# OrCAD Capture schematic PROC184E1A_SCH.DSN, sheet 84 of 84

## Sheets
84 62. AUDIO I/F - STEREO MIC #1: size C; title: AUDIO I/F - STEREO MIC #1; note: PROC184_SCH
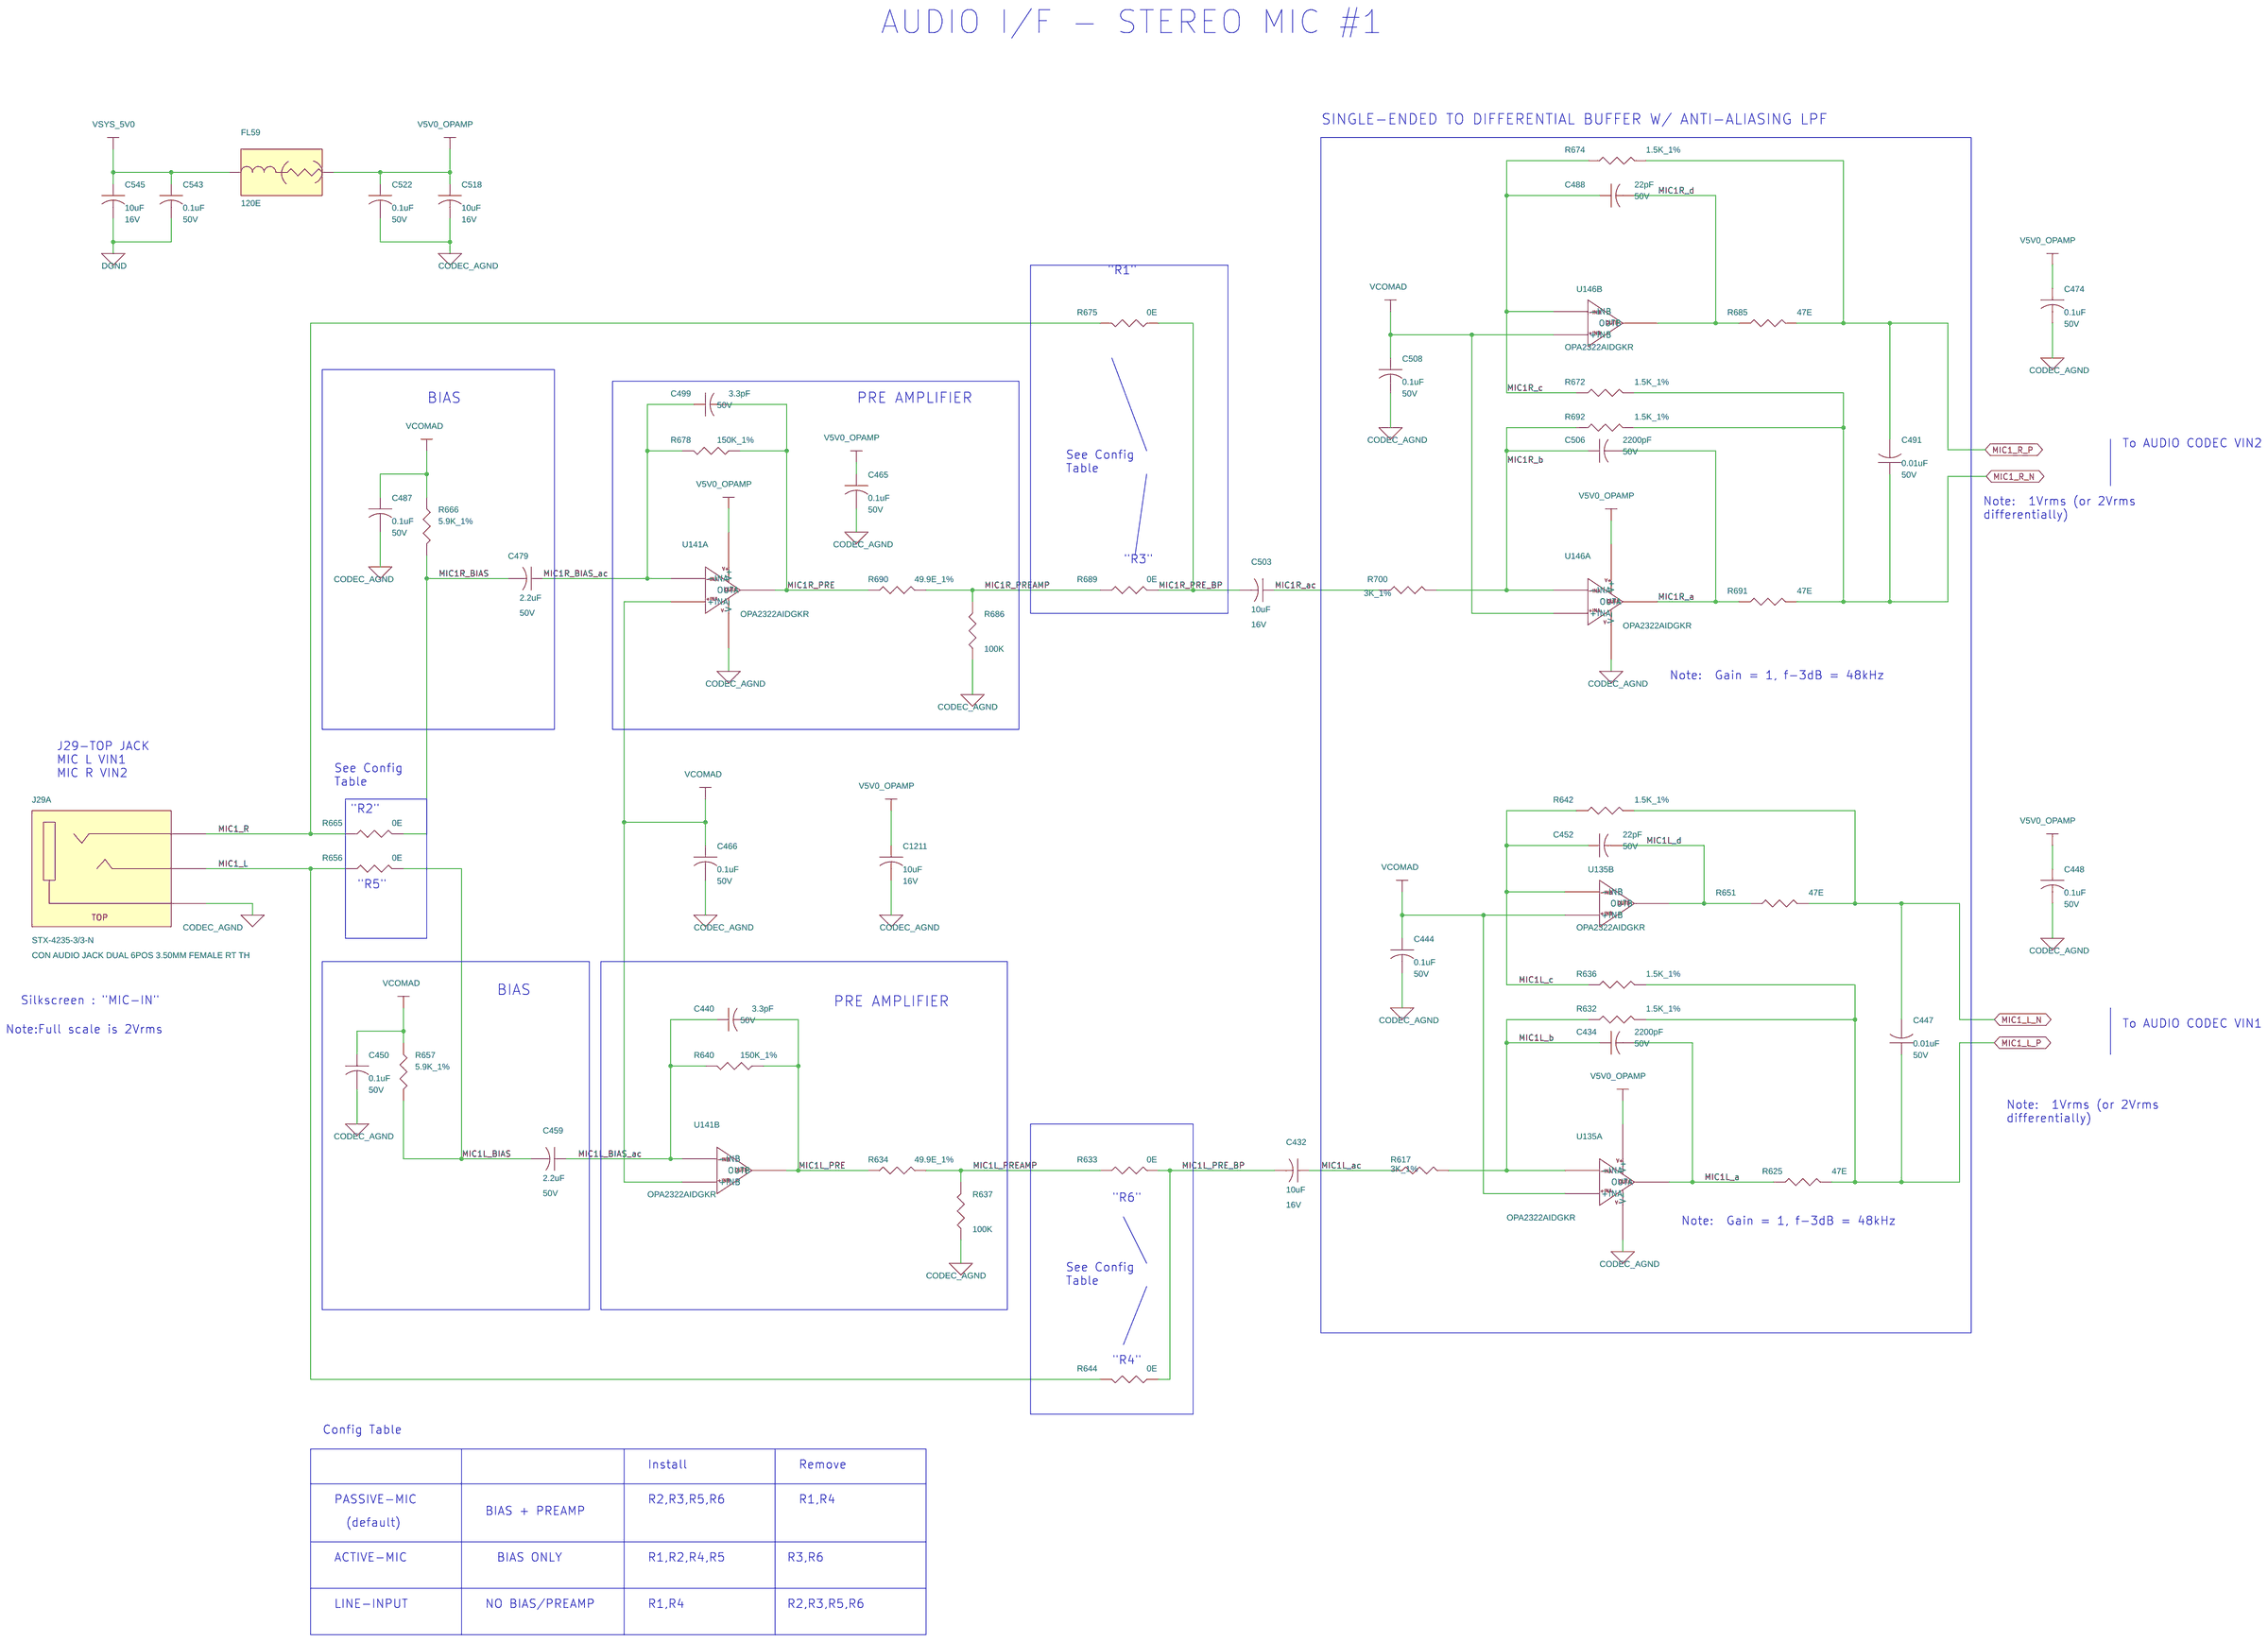
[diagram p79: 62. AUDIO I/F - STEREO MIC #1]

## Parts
C432  10uF  [CAP0805_1-5]
C434  2200pF  [CAP0805_1-5]
C440  3.3pF  [CAP0402_0-75]
C444  0.1uF  [CAP0402_0-75]
C447  0.01uF  [CAP0402_0-75]
C448  0.1uF  [CAP0402_0-75]
C450  0.1uF  [CAP0402_0-75]
C452  22pF  [CAP0402_0-75]
C459  2.2uF  [CAP0805_1-5]
C465  0.1uF  [CAP0402_0-75]
C466  0.1uF  [CAP0402_0-75]
C474  0.1uF  [CAP0402_0-75]
C479  2.2uF  [CAP0805_1-5]
C487  0.1uF  [CAP0402_0-75]
C488  22pF  [CAP0402_0-75]
C491  0.01uF  [CAP0402_0-75]
C499  3.3pF  [CAP0402_0-75]
C503  10uF  [CAP0805_1-5]
C506  2200pF  [CAP0805_1-5]
C508  0.1uF  [CAP0402_0-75]
C518  10uF  [CAP0805_1-5]
C522  0.1uF  [CAP0402_0-75]
C543  0.1uF  [CAP0402_0-75]
C545  10uF  [CAP0805_1-5]
C1211  10uF  [CAP0805_1-5]
FL59  120E  [EMIFIL_BLM15A_0402_0-6]
J29  CON_AUDIOJACK6_STX-4235  [CON_AV6_STX-4235-3-3_S_R_T_26]  (sections A,B)
R617  3K_1%  [RES0402_0-5]
R625  47E  [RES0402_0-5]
R632  1.5K_1%  [RES0402_0-5]
R633  0E  [RES0402_0-5]
R634  49.9E_1%  [RES0402_0-5]
R636  1.5K_1%  [RES0402_0-5]
R637  100K  [RES0402_0-5]
R640  150K_1%  [RES0402_0-5]
R642  1.5K_1%  [RES0402_0-5]
R644  0E  [RES0402_0-5]
R651  47E  [RES0402_0-5]
R656  0E  [RES0402_0-5]
R657  5.9K_1%  [RES0402_0-5]
R665  0E  [RES0402_0-5]
R666  5.9K_1%  [RES0402_0-5]
R672  1.5K_1%  [RES0402_0-5]
R674  1.5K_1%  [RES0402_0-5]
R675  0E  [RES0402_0-5]
R678  150K_1%  [RES0402_0-5]
R685  47E  [RES0402_0-5]
R686  100K  [RES0402_0-5]
R689  0E  [RES0402_0-5]
R690  49.9E_1%  [RES0402_0-5]
R691  47E  [RES0402_0-5]
R692  1.5K_1%  [RES0402_0-5]
R700  3K_1%  [RES0402_0-5]
U135  OPA2322AIDGKR  [VSSOP8_25-59_120X120_1-1]  (sections A,B)
U141  OPA2322AIDGKR  [VSSOP8_25-59_120X120_1-1]  (sections A,B)
U146  OPA2322AIDGKR  [VSSOP8_25-59_120X120_1-1]  (sections A,B)

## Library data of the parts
C432 C503 C518 C545 C1211 = CAP: CAP CERAMIC 10uF 16V 10% X5R 0805; Automotive Alternate_mfr_name: TDK; Automotive Alternate_mfr_part_number: CGA4J1X7S1C106K125AC; Chkd/date: SHREESHAIL/220506; Crtd /date: MAZHAR/150506; Custom_Duty: 15%; Customs_HS_Code: 85322990; Direct Alternate_mfr_name: TDK; Direct Alternate_mfr_part_number: C2012X7S1C106K125AC; Distributor_name: DIGIKEY; Distributor_part_number: 490-3886-1-ND; Footprint Path: Y:\MIS_DATABASE\Library\ALTIUM_TOOL\PCB_FOOTPRINTS\Altium_Footprint_Lib.PcbLib; Height: 1.35MM; Library Path: Y:\MIS_DATABASE\Library\ALTIUM_TOOL\SCHEMATICS_PARTS\MS_DISCRETE_Library.schlib; Manufacturer: MURATA; Mfr_name: MURATA; Mfr_part_number: GRM21BR61C106KE15L; Mistral Part No: 120009030205-R; Package: 0805; Part_type: CAPACITORS\CERAMIC; Project: VOCERA; RoHS: RoHS; Temperature: -55°C+85°C; Tolerance: 10%; Voltage: 16V; Wattage: NA; Weight: 9.5mg; Datasheet: Y:\MIS_DATABASE\DATASHEETS\CAPACITORS\MURATA-GXX-SER_NOV17.PDF
C434 C506 = CAP: CAP CERAMIC 2200pF 50V 1% C0G(NP0) 0805; Automotive Alternate_mfr_name: TDK; Automotive Alternate_mfr_part_number: CGA4C2C0G1H222J060AA; Chkd/date: MANIRAJA/070619; Crtd /date: MANIRAJA/070619; Custom_Duty: 15%; Customs_HS_Code: 85322990; Direct Alternate_mfr_name: TDK; Direct Alternate_mfr_part_number: C2012C0G1H222J060AA; Distributor_name: DIGIKEY; Distributor_part_number: 311-4157-1-ND; Footprint Path: Y:\MIS_DATABASE\Library\ALTIUM_TOOL\PCB_FOOTPRINTS\Altium_Footprint_Lib.PcbLib; Height: 1.45MM; Library Path: Y:\MIS_DATABASE\Library\ALTIUM_TOOL\SCHEMATICS_PARTS\MS_DISCRETE_Library.schlib; Manufacturer: YAGEO AMERICA; Mfr_name: YAGEO AMERICA; Mfr_part_number: CC0805FKNPO9BN222; Mistral Part No: 120011120002-R; Package: 0805; Part_type: CAPACITORS\CERAMIC; Project: J7ES_SOM_DUAL-LEO_PMIC; RoHS: RoHS; Temperature: -55°C+125°C; Tolerance: 1%; Voltage: 50V; Wattage: NA; Weight: 5.5mg; Datasheet: Y:\MIS_DATABASE\DATASHEETS\CAPACITORS\YACC-NPO.PDF
C440 C499 = CAP: CAP CERAMIC 3.3pF 50V 0.25pF C0G(NP0) 0402; Automotive Alternate_mfr_name: TDK; Automotive Alternate_mfr_part_number: CGA2B2C0G1H3R3C050BA; Chkd/date: SHREESHAIL/281105; Crtd /date: MAZHAR/211005; Custom_Duty: 15%; Customs_HS_Code: 85322990; Direct Alternate_mfr_name: SAMSUNG; Direct Alternate_mfr_part_number: CL05C3R3CB5NNNC; Distributor_name: DIGIKEY; Distributor_part_number: 478-1064-1-ND; Footprint Path: Y:\MIS_DATABASE\Library\ALTIUM_TOOL\PCB_FOOTPRINTS\Altium_Footprint_Lib.PcbLib; Height: 0.56MM; Library Path: Y:\MIS_DATABASE\Library\ALTIUM_TOOL\SCHEMATICS_PARTS\MS_DISCRETE_Library.schlib; Manufacturer: AVX CORPORATION; Mfr_name: AVX CORPORATION; Mfr_part_number: 04025A3R3CAT2A; Mistral Part No: 120009030354-R; Package: 0402; Part_type: CAPACITORS\CERAMIC; Project: EPDA_CORE; RoHS: RoHS; Temperature: -55°C+125°C; Tolerance: 0.25pF%; Voltage: 50V; Wattage: NA; Weight: 0.65mg; Datasheet: Y:\MIS_DATABASE\DATASHEETS\CAPACITORS\AVX_MLC.PDF
C444 C448 C450 C465 C466 C474 C487 C508 C522 C543 = CAP: CAP CERAMIC 0.1uF 50V 10% X7R 0402; Automotive Alternate_mfr_name: TDK; Automotive Alternate_mfr_part_number: CGA2B3X7R1H104K050BB; Chkd/date: MANIRAJA/261020; Crtd /date: ALVY/211020; Custom_Duty: 15%; Customs_HS_Code: 85322990; Direct Alternate_mfr_name: TDK; Direct Alternate_mfr_part_number: C1005X7R1H104K050BE; Distributor_name: DIGIKEY; Distributor_part_number: 490-10700-1-ND; Footprint Path: Y:\MIS_DATABASE\Library\ALTIUM_TOOL\PCB_FOOTPRINTS\Altium_Footprint_Lib.PcbLib; Height: 0.55MM; Library Path: Y:\MIS_DATABASE\Library\ALTIUM_TOOL\SCHEMATICS_PARTS\MS_DISCRETE_Library.schlib; Manufacturer: MURATA; Mfr_name: MURATA; Mfr_part_number: GRM155R71H104KE14D; Mistral Part No: 120011100014-R; Package: 0402; Part_type: CAPACITORS\CERAMIC; Project: J7_CP; RoHS: RoHS; Temperature: -55°C+125°C; Tolerance: 10%; Voltage: 50V; Wattage: NA; Weight: 3.1mg; Datasheet: Y:\MIS_DATABASE\DATASHEETS\CAPACITORS\GRM155R71H104KE14.PDF
C447 C491 = CAP: CAP CERAMIC 0.01uF 50V 10% X7R 0402; Automotive Alternate_mfr_name: TDK; Automotive Alternate_mfr_part_number: CGA2B2X7R1E103K050BA; Chkd/date: MANIRAJA/280319; Crtd /date: MANIRAJA/280319; Custom_Duty: 15%; Customs_HS_Code: 85322990; Direct Alternate_mfr_name: YAGEO AMERICA; Direct Alternate_mfr_part_number: CC0402KRX7R8BB103; Distributor_name: DIGIKEY; Distributor_part_number: 490-4516-1-ND; Footprint Path: Y:\MIS_DATABASE\Library\ALTIUM_TOOL\PCB_FOOTPRINTS\Altium_Footprint_Lib.PcbLib; Height: 0.55MM; Library Path: Y:\MIS_DATABASE\Library\ALTIUM_TOOL\SCHEMATICS_PARTS\MS_DISCRETE_Library.schlib; Manufacturer: MURATA; Mfr_name: MURATA; Mfr_part_number: GRM155R71H103KA88D; Mistral Part No: 120009030025-R; Package: 0402; Part_type: CAPACITORS\CERAMIC; Project: G4_SVGA; RoHS: RoHS; Temperature: -55°C+125°C; Tolerance: 10%; Voltage: 50V; Wattage: NA; Weight: 0.65mg; Datasheet: Y:\MIS_DATABASE\DATASHEETS\CAPACITORS\GRM155R71H103KA88D.PDF
C452 C488 = CAP: CAP CERAMIC 22pF 50V 5% C0G(NP0) 0402; Automotive Alternate_mfr_name: TDK; Automotive Alternate_mfr_part_number: CGA2B2C0G1H220J050BA; Chkd/date: MANIRAJA/060619; Crtd /date: MANIRAJA/060619; Custom_Duty: 15%; Customs_HS_Code: 85322990; Direct Alternate_mfr_name: TDK; Direct Alternate_mfr_part_number: C1005NP01H220J050BA; Distributor_name: DIGIKEY; Distributor_part_number: 1276-1116-1-ND; Footprint Path: Y:\MIS_DATABASE\Library\ALTIUM_TOOL\PCB_FOOTPRINTS\Altium_Footprint_Lib.PcbLib; Height: 0.55MM; Library Path: Y:\MIS_DATABASE\Library\ALTIUM_TOOL\SCHEMATICS_PARTS\MS_DISCRETE_Library.schlib; Manufacturer: SAMSUNG; Mfr_name: SAMSUNG; Mfr_part_number: CL05C220JB5NNNC; Mistral Part No: 120014100023-R; Package: 0402; Part_type: CAPACITORS\CERAMIC; Project: J7ES_SOM_DUAL-LEO_PMIC; RoHS: RoHS; Temperature: -55°C+125°C; Tolerance: 5%; Voltage: 50V; Wattage: NA; Weight: 0.65mg; Datasheet: Y:\MIS_DATABASE\DATASHEETS\CAPACITORS\CL05C220JB5NNNC.PDF
C459 C479 = CAP: CAP CERAMIC 2.2uF 50V 20% X7R 0805; Automotive Alternate_mfr_name: TDK; Automotive Alternate_mfr_part_number: CGA4J3X7R1H225K125AB; Chkd/date: MANIRAJA/241018; Crtd /date: ALVY/241018; Custom_Duty: 15%; Customs_HS_Code: 85322990; Direct Alternate_mfr_name: YAGEO AMERICA; Direct Alternate_mfr_part_number: CC0805KKX7R9BB225; Distributor_name: DIGIKEY; Distributor_part_number: 445-172488-1-ND; Footprint Path: Y:\MIS_DATABASE\Library\ALTIUM_TOOL\PCB_FOOTPRINTS\Altium_Footprint_Lib.PcbLib; Height: 1.50MM; Library Path: Y:\MIS_DATABASE\Library\ALTIUM_TOOL\SCHEMATICS_PARTS\MS_DISCRETE_Library.schlib; Manufacturer: TDK CORPORATION; Mfr_name: TDK CORPORATION; Mfr_part_number: C2012X7R1H225M125AE; Mistral Part No: 120018100054-R; Package: 0805; Part_type: CAPACITORS\CERAMIC; Project: TI_J7ES_EVM_CP; RoHS: RoHS; Temperature: -55°C+125°C; Tolerance: 20%; Voltage: 50V; Wattage: NA; Weight: 5.5mg; Datasheet: Y:\MIS_DATABASE\DATASHEETS\CAPACITORS\TDK-CAP-E-SER.PDF
FL59 = EMIFILTER_IND: IND FERRITE BEAD CHIP 120E 1.3A 0402; Automotive Alternate_mfr_name: TDK; Automotive Alternate_mfr_part_number: MPZ1005S121CTD25; Chkd/date: VASANTHA/010117; Crtd /date: CHAITHANYA/150312; Custom_Duty: 24%; Customs_HS_Code: 85437099; Direct Alternate_mfr_name: TDK; Direct Alternate_mfr_part_number: MPZ1005S121CT000; Distributor_name: DIGIKEY; Distributor_part_number: 490-5203-1-ND; Footprint Path: Y:\MIS_DATABASE\Library\ALTIUM_TOOL\PCB_FOOTPRINTS\Altium_Footprint_Lib.PcbLib; Height: 0.55MM; Library Path: Y:\MIS_DATABASE\Library\ALTIUM_TOOL\SCHEMATICS_PARTS\MS_FILTER_Library.schlib; Manufacturer: MURATA; Mfr_name: MURATA; Mfr_part_number: BLM15PD121SN1D; Mistral Part No: 130012030043-R; Package: 0402; Part_type: FILTER; Project: GEN_3-8; RoHS: RoHS; Temperature: -55°C+125°C; Tolerance: 25%; Voltage: NA; Wattage: NA; Weight: 0.65mg; Datasheet: Y:\MIS_DATABASE\DATASHEETS\DISCRETES\INDUCTORS\BLM15X-SER.PDF
J29 = CON_AUDIOJACK6_STX-4235-3_3: CON AUDIO JACK DUAL 6POS 3.50MM FEMALE RT TH; Chkd/date: MANIRAJA/090818; Crtd /date: ALVY/080818; Custom_Duty: 24%; Customs_HS_Code: 85369090; Distributor_name: MOUSER; Distributor_part_number: 806-STX-4235-3/3-N; Footprint Path: Y:\MIS_DATABASE\Library\ALTIUM_TOOL\PCB_FOOTPRINTS\Altium_Footprint_Lib.PcbLib; Height: 26.00MM; Library Path: Y:\MIS_DATABASE\Library\ALTIUM_TOOL\SCHEMATICS_PARTS\MS_CONNECTOR_Library.schlib; Library Ref: CON_AUDIOJACK6_STX-4235-3/3; Manufacturer: KYCON; Mfr_name: KYCON; Mfr_part_number: STX-4235-3/3-N; Mistral Part No: 150018080005-R; Package: THRU-HOLE; Part_type: CONNECTOR\JACK; Project: TI_J7ES_EVM_FUSION2_SER_CAP; RoHS: RoHS; Temperature: -25°C+85°C; Tolerance: NA; Voltage: NA; Wattage: NA; Weight: NA; Datasheet: Y:\MIS_DATABASE\DATASHEETS\CONNECTORS\STX-4235-3-3-N.PDF
R617 R700 = RESISTOR: RES 3K 1/16W 1% 0402; Chkd/date: MANIRAJA/101117; Crtd /date: MANIRAJA/101117; Custom_Duty: 15%; Customs_HS_Code: 85332119; Distributor_name: DIGIKEY; Distributor_part_number: 311-3KLRCT-ND; Footprint Path: Y:\MIS_DATABASE\Library\ALTIUM_TOOL\PCB_FOOTPRINTS\Altium_Footprint_Lib.PcbLib; Height: 0.40MM; Library Path: Y:\MIS_DATABASE\Library\ALTIUM_TOOL\SCHEMATICS_PARTS\MS_DISCRETE_Library.schlib; Manufacturer: PANASONIC-ECG; Mfr_name: YAGEO AMERICA; Mfr_part_number: RC0402FR-073KL; Mistral Part No: 110017110004-R; Package: 0402; Part_type: RESISTORS\FIXED; Project: TI_SVB_MAXWELL_DUT; RoHS: RoHS; Temperature: -55°C+155°C; Tolerance: 1%; Voltage: NA; Wattage: 1/16W; Weight: 0.65mg; Datasheet: Y:\MIS_DATABASE\DATASHEETS\RESISTORS\RCXXXXL-SER_MAR18.PDF
R625 R651 R685 R691 = RESISTOR: RES 47E 1/16W 5% 0402; Chkd/date: MANIRAJA/250319; Crtd /date: MANIRAJA/250319; Custom_Duty: 15%; Customs_HS_Code: 85332119; Distributor_name: DIGIKEY; Distributor_part_number: 311-47JRCT-ND; Footprint Path: Y:\MIS_DATABASE\Library\ALTIUM_TOOL\PCB_FOOTPRINTS\Altium_Footprint_Lib.PcbLib; Height: 0.40MM; Library Path: Y:\MIS_DATABASE\Library\ALTIUM_TOOL\SCHEMATICS_PARTS\MS_DISCRETE_Library.schlib; Manufacturer: YAGEO AMERICA; Mfr_name: YAGEO AMERICA; Mfr_part_number: RC0402JR-0747RL; Mistral Part No: 110019040221-R; Package: 0402; Part_type: RESISTORS\FIXED; Project: POWERBOX; RoHS: RoHS; Temperature: -55°C+155°C; Tolerance: 5%; Voltage: NA; Wattage: 1/16W; Weight: 0.65mg; Datasheet: Y:\MIS_DATABASE\DATASHEETS\RESISTORS\RCXXXXL-SER_MAR18.PDF
R632 R636 R642 R672 R674 R692 = RESISTOR: RES 1.5K 1/16W 1% 0402; Chkd/date: VASANTHA/201216; Crtd /date: JEBRAN/250815; Custom_Duty: 15%; Customs_HS_Code: 85332119; Distributor_name: DIGIKEY; Distributor_part_number: 311-1.50KLRCT-ND; Footprint Path: Y:\MIS_DATABASE\Library\ALTIUM_TOOL\PCB_FOOTPRINTS\Altium_Footprint_Lib.PcbLib; Height: 0.40MM; Library Path: Y:\MIS_DATABASE\Library\ALTIUM_TOOL\SCHEMATICS_PARTS\MS_DISCRETE_Library.schlib; Manufacturer: YAGEO AMERICA; Mfr_name: YAGEO AMERICA; Mfr_part_number: RC0402FR-071K5L; Mistral Part No: 110015080041-R; Package: 0402; Part_type: RESISTORS\FIXED; Project: OCTBTS3600; RoHS: RoHS; Temperature: -55°C+155°C; Tolerance: 1%; Voltage: NA; Wattage: 1/16W; Weight: 0.65mg; Datasheet: Y:\MIS_DATABASE\DATASHEETS\RESISTORS\RCXXXXL-SER_MAR18.PDF
R633 R656 R665 R689 = RESISTOR: RES 0E 1/10W JUMPER 0402; Chkd/date: VASANTHA/061216; Crtd /date: NAVEED/201014; Custom_Duty: 15%; Customs_HS_Code: 85332119; Distributor_name: DIGIKEY; Distributor_part_number: P0.0JCT-ND; Footprint Path: Y:\MIS_DATABASE\Library\ALTIUM_TOOL\PCB_FOOTPRINTS\Altium_Footprint_Lib.PcbLib; Height: 0.40MM; IBISSP_MODLES: VALUE REPEATING 2 TIME; Library Path: Y:\MIS_DATABASE\Library\ALTIUM_TOOL\SCHEMATICS_PARTS\MS_DISCRETE_Library.schlib; Manufacturer: PANASONIC-ECG; Mfr_name: PANASONIC-ECG; Mfr_part_number: ERJ-2GE0R00X; Mistral Part No: 110018030052-R; Package: 0402; Part_type: RESISTORS\FIXED; Project: AEGIS POM; RoHS: RoHS; Temperature: -55°C+155°C; Tolerance: NA; Voltage: NA; Wattage: 1/10W; Weight: 0.8mg; Datasheet: Y:\MIS_DATABASE\DATASHEETS\RESISTORS\PAN-ERJSER_NOV17.PDF
R634 R690 = RESISTOR: RES 49.9E 1/10W 1% 0402; Chkd/date: VASANTHA/201216; Crtd /date: MAZHAR/201005; Custom_Duty: 15%; Customs_HS_Code: 85332119; Distributor_name: DIGIKEY; Distributor_part_number: P49.9LCT-ND; Footprint Path: Y:\MIS_DATABASE\Library\ALTIUM_TOOL\PCB_FOOTPRINTS\Altium_Footprint_Lib.PcbLib; Height: 0.40MM; Library Path: Y:\MIS_DATABASE\Library\ALTIUM_TOOL\SCHEMATICS_PARTS\MS_DISCRETE_Library.schlib; Manufacturer: PANASONIC-ECG; Mfr_name: PANASONIC-ECG; Mfr_part_number: ERJ-2RKF49R9X; Mistral Part No: 110009030897-R; Package: 0402; Part_type: RESISTORS\FIXED; Project: RED EYE; RoHS: RoHS; Temperature: -55°C+155°C; Tolerance: 1%; Voltage: NA; Wattage: 1/10W; Weight: 0.8mg; Datasheet: Y:\MIS_DATABASE\DATASHEETS\RESISTORS\PAN-ERJSER_NOV17.PDF
R637 R686 = RESISTOR: RES 100K 1/10W 5% 0402; Assembly_Instruction: DNI; Chkd/date: VASANTHA/291216; Crtd /date: GEETHA/190406; Custom_Duty: 15%; Customs_HS_Code: 85332119; Distributor_name: DIGIKEY; Distributor_part_number: P100KJCT-ND; Footprint Path: Y:\MIS_DATABASE\Library\ALTIUM_TOOL\PCB_FOOTPRINTS\Altium_Footprint_Lib.PcbLib; Height: 0.40MM; Library Path: Y:\MIS_DATABASE\Library\ALTIUM_TOOL\SCHEMATICS_PARTS\MS_DISCRETE_Library.schlib; Manufacturer: PANASONIC-ECG; Mfr_name: PANASONIC-ECG; Mfr_part_number: ERJ-2GEJ104X; Mistral Part No: 110009030177-R; Package: 0402; Part_type: RESISTORS\FIXED; Project: RED EYE; RoHS: RoHS; Temperature: -55°C+155°C; Tolerance: 5%; Voltage: NA; Wattage: 1/10W; Weight: 0.8mg; Datasheet: Y:\MIS_DATABASE\DATASHEETS\RESISTORS\PAN-ERJSER_NOV17.PDF
R640 R678 = RESISTOR: RES 150K 1/10W 1% 0402; Chkd/date: SHREESHAIL/200906; Crtd /date: MAZHAR/190906; Custom_Duty: 15%; Customs_HS_Code: 85332119; Distributor_name: DIGIKEY; Distributor_part_number: P150KLCT-ND; Footprint Path: Y:\MIS_DATABASE\Library\ALTIUM_TOOL\PCB_FOOTPRINTS\Altium_Footprint_Lib.PcbLib; Height: 0.40MM; Library Path: Y:\MIS_DATABASE\Library\ALTIUM_TOOL\SCHEMATICS_PARTS\MS_DISCRETE_Library.schlib; Manufacturer: PANASONIC-ECG; Mfr_name: PANASONIC-ECG; Mfr_part_number: ERJ-2RKF1503X; Mistral Part No: 110009030336-R; Package: 0402; Part_type: RESISTORS\FIXED; Project: SM2_AFE; RoHS: RoHS; Temperature: -55°C+155°C; Tolerance: 1%; Voltage: NA; Wattage: 1/10W; Weight: 0.8mg; Datasheet: Y:\MIS_DATABASE\DATASHEETS\RESISTORS\PAN-ERJSER_NOV17.PDF
R644 R675 = RESISTOR: RES 0E 1/10W JUMPER 0402; Assembly_Instruction: DNI; Chkd/date: VASANTHA/061216; Crtd /date: NAVEED/201014; Custom_Duty: 15%; Customs_HS_Code: 85332119; Distributor_name: DIGIKEY; Distributor_part_number: P0.0JCT-ND; Footprint Path: Y:\MIS_DATABASE\Library\ALTIUM_TOOL\PCB_FOOTPRINTS\Altium_Footprint_Lib.PcbLib; Height: 0.40MM; IBISSP_MODLES: VALUE REPEATING 2 TIME; Library Path: Y:\MIS_DATABASE\Library\ALTIUM_TOOL\SCHEMATICS_PARTS\MS_DISCRETE_Library.schlib; Manufacturer: PANASONIC-ECG; Mfr_name: PANASONIC-ECG; Mfr_part_number: ERJ-2GE0R00X; Mistral Part No: 110018030052-R; Package: 0402; Part_type: RESISTORS\FIXED; Project: AEGIS POM; RoHS: RoHS; Temperature: -55°C+155°C; Tolerance: NA; Voltage: NA; Wattage: 1/10W; Weight: 0.8mg; Datasheet: Y:\MIS_DATABASE\DATASHEETS\RESISTORS\PAN-ERJSER_NOV17.PDF
R657 R666 = RESISTOR: RES 5.9K 1/10W 1% 0402; Chkd/date: MAZHAR/251110; Crtd /date: BAVISH/251110; Custom_Duty: 15%; Customs_HS_Code: 85332119; Distributor_name: DIGIKEY; Distributor_part_number: P5.90KLCT-ND; Footprint Path: Y:\MIS_DATABASE\Library\ALTIUM_TOOL\PCB_FOOTPRINTS\Altium_Footprint_Lib.PcbLib; Height: 0.40MM; Library Path: Y:\MIS_DATABASE\Library\ALTIUM_TOOL\SCHEMATICS_PARTS\MS_DISCRETE_Library.schlib; Manufacturer: PANASONIC-ECG; Mfr_name: PANASONIC-ECG; Mfr_part_number: ERJ-2RKF5901X; Mistral Part No: 110010110029-R; Package: 0402; Part_type: RESISTORS\FIXED; Project: CENTAURUS; RoHS: RoHS; Temperature: -55°C+155°C; Tolerance: 1%; Voltage: NA; Wattage: 1/10W; Weight: 0.8mg; Datasheet: Y:\MIS_DATABASE\DATASHEETS\RESISTORS\PAN-ERJSER_NOV17.PDF
U135 U141 U146 = OPA2350UA_SOIC8: IC 20MHz 1.8V LOW NOISE RRI/O CMOS OPAMP VSSOP8; Automotive Alternate_mfr_name: TEXAS INSTRUMENTS; Automotive Alternate_mfr_part_number: OPA2322AQDGKRQ1; Chkd/date: MANIRAJA/161018; Crtd /date: ALVY/161018; Custom_Duty: 15%; Customs_HS_Code: 85423100; Distributor_name: DIGIKEY; Distributor_part_number: 296-41349-1-ND; Footprint Path: Y:\MIS_DATABASE\Library\ALTIUM_TOOL\PCB_FOOTPRINTS\Altium_Footprint_Lib.PcbLib; Height: 1.10MM; Library Path: Y:\MIS_DATABASE\Library\ALTIUM_TOOL\SCHEMATICS_PARTS\MS_OPAMP_Library.schlib; Manufacturer: TEXAS INSTRUMENTS; Mfr_name: TEXAS INSTRUMENTS; Mistral Part No: 140118100019-R; Package: VSSOP8; Part_type: ICS\ANALOG\OPAMP; Project: TI_J7ES_EVM_CP; RoHS: RoHS; Temperature: -40°C+125°C; Tolerance: NA; Voltage: NA; Wattage: NA; Weight: 26.5mg; Datasheet: Y:\MIS_DATABASE\DATASHEETS\ICS\OPAMP\OPA2322XX.PDF

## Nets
DGND: C444.2 C448.2 C450.2 C465.2 C466.2 C474.2 C487.2 C508.2 C518.2 C522.2 C543.2 C545.2 C1211.2 J29.1A R637.1 R686.1 U135.4(V-) U141.4(V-) U146.4(V-) ; also on sheet 11 12 13 14 15 16 17 18 20 21 22 23 24 25 26 27 28 29 30 31 32 33 34 35 36 37 38 39 40 41 42 43 44 45 46 47 48 49 50 51 52 53 54 55 56 57 58 59 60 61 62 63 64 65 66 67 68 69 70 71 72 73 76 77 78 79 81 82 83
V5V0_OPAMP: C448.1 C465.1 C474.1 C518.1 C522.1 C1211.1 FL59.2 U135.8(V+) U141.8(V+) U146.8(V+) ; also on sheet 82
MIC1_L: J29.5A R644.2 R656.1
MIC1_L_N: C447.2 R642.2 R651.2 ; also on sheet 82
MIC1_L_P: C447.1 R625.2 R632.2 R636.2 ; also on sheet 82
MIC1_R: J29.2A R665.1 R675.2
MIC1_R_N: C491.1 R672.2 R691.2 R692.2 ; also on sheet 82
MIC1_R_P: C491.2 R674.2 R685.2 ; also on sheet 82
MIC1L_a: C434.2 R625.1 U135.1(OUTA)
MIC1L_ac: C432.1 R617.1
MIC1L_b: C434.1 R617.2 R632.1 U135.2(-INA)
MIC1L_BIAS: C459.2 R656.2 R657.2
MIC1L_BIAS_ac: C440.1 C459.1 R640.2 U141.6(-INB)
MIC1L_c: C452.1 R636.1 R642.1 U135.6(-INB)
MIC1L_d: C452.2 R651.1 U135.7(OUTB)
MIC1L_PRE: C440.2 R634.1 R640.1 U141.7(OUTB)
MIC1L_PRE_BP: C432.2 R633.2 R644.1
MIC1L_PREAMP: R633.1 R634.2 R637.2
MIC1R_a: C506.2 R691.1 U146.1(OUTA)
MIC1R_ac: C503.1 R700.1
MIC1R_b: C506.1 R692.1 R700.2 U146.2(-INA)
MIC1R_BIAS: C479.2 R665.2 R666.2
MIC1R_BIAS_ac: C479.1 C499.1 R678.2 U141.2(-INA)
MIC1R_c: C488.1 R672.1 R674.1 U146.6(-INB)
MIC1R_d: C488.2 R685.1 U146.7(OUTB)
MIC1R_PRE: C499.2 R678.1 R690.1 U141.1(OUTA)
MIC1R_PRE_BP: C503.2 R675.1 R689.2
MIC1R_PREAMP: R686.2 R689.1 R690.2
VCOMAD: C444.1 C450.1 C466.1 C487.1 C508.1 R657.1 R666.1 U135.3(+INA) U135.5(+INB) U141.3(+INA) U141.5(+INB) U146.3(+INA) U146.5(+INB) ; also on sheet 82
VSYS_5V0: C543.1 C545.1 FL59.1 ; also on sheet 20 30 31 50 52 59 65 68 72 81 82 83

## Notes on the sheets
sheet 84
- AUDIO I/F - STEREO MIC #1
- SINGLE-ENDED TO DIFFERENTIAL BUFFER W/ ANTI-ALIASING LPF
- "R1"
- BIAS
- PRE AMPLIFIER
- To AUDIO CODEC VIN2
- See Config
  Table
- Note:  1Vrms (or 2Vrms
  differentially)
- "R3"
- Note:  Gain = 1, f-3dB = 48kHz
- J29-TOP JACK
  MIC L VIN1
  MIC R VIN2
- See Config
  Table
- "R2"
- "R5"
- BIAS
- Silkscreen : "MIC-IN"
- PRE AMPLIFIER
- Note:Full scale is 2Vrms
- To AUDIO CODEC VIN1
- Note:  1Vrms (or 2Vrms
  differentially)
- "R6"
- Note:  Gain = 1, f-3dB = 48kHz
- See Config
  Table
- "R4"
- Config Table
- Install
- Remove
- PASSIVE-MIC
- R2,R3,R5,R6
- R1,R4
- BIAS + PREAMP
- (default)
- ACTIVE-MIC
- BIAS ONLY
- R1,R2,R4,R5
- R3,R6
- LINE-INPUT
- NO BIAS/PREAMP
- R1,R4
- R2,R3,R5,R6
